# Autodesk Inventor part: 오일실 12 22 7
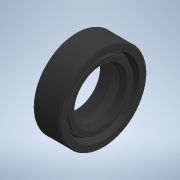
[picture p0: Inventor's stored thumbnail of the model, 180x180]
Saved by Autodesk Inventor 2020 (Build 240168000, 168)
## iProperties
Created: 2024-05
Part Number: 오일실 12 22 7
Material: 고무
Description: 오일-실
Document SubType Name: Modeling
Designer: oem
Density: 0.93 g/cm^3
Appearance: 기본값
Author: jhkim
Sending System: Autodesk Inventor 2025
Preprocessor: ST-DEVELOPER v20
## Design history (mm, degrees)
feature "Solid1"
node "솔리드1"
